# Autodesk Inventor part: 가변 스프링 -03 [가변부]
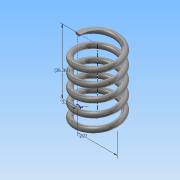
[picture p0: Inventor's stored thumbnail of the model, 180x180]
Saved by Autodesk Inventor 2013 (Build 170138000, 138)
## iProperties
Created: 2014-12
Part Number: 가변 스프링 -03 [가변부]
Material: 강철, 탄소
Document SubType Name: Modeling
Designer: Administrator
Density: 7.87 g/cm^3
Mass: 18.8875 g
Surface Area: 32.5169 cm^2
Volume: 2.39994 cm^3
Author: Administrator
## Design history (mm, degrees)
sketch "Sketch1"
  geometry: L1 (0, 0)-(11, 0); L2 (11, 0)-(11, 36.261); L3 (11, 36.261)-(0, 36.261); L4 (0, 36.261)-(0, 0); C1 r 1.5 at (11, 0)
  constraints: 8 end point, 2 parallel, 1 centre point, 1 coincident, 1 horizontal, 1 perpendicular
  dimensions: "d0" = 3 diameter of C1; "d1" = 22 diameter of L2 L4; "d2" = 36.2612 distance between parallel lines of L1 L3 (derived)
coil "Coil1" pitch "d3" = 10; turns "d5" = 5; dims "d4" = 36.2612 (= d2), "d6" = 0, angle "d7" = 90 deg, angle "d8" = 90 deg, "d9" = 0, "d10" = 0
sketch "Sketch2"
  geometry: L1 (-12.5, 0)-(-9.5, 0) reference; 1 further point
  constraints: 1 horizontal alignment
extrude "Extrusion1" cut sketch "Sketch2" stored distance "d11" = 10; taper "d12" = 0 deg
workplane "Work Plane2"
sketch "Sketch3"
  geometry: L1 (1.5, 0)-(-1.5, 0) reference; 1 further point
  constraints: 1 horizontal alignment
extrude "Extrusion2" cut sketch "Sketch3" stored distance "d14" = 10; taper "d15" = 0 deg
body "Solid1"
node "Project Cut Edges1"
node "Project Cut Edges2"
other parameters: "d13" = 0
